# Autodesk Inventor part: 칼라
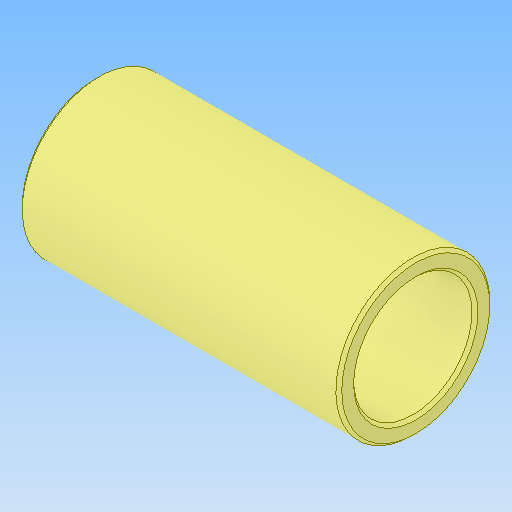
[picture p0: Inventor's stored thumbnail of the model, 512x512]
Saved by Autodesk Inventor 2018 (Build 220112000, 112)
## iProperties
Created: 2024-09
Part Number: 칼라
Material: 강철, 연강
Document SubType Name: Modeling
Designer: home
Density: 7.85 g/cm^3
Appearance: 기본값
Author: jhkim
Sending System: Autodesk Inventor 2025
Preprocessor: ST-DEVELOPER v20
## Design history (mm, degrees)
feature "솔리드1"
node "솔리드2"
